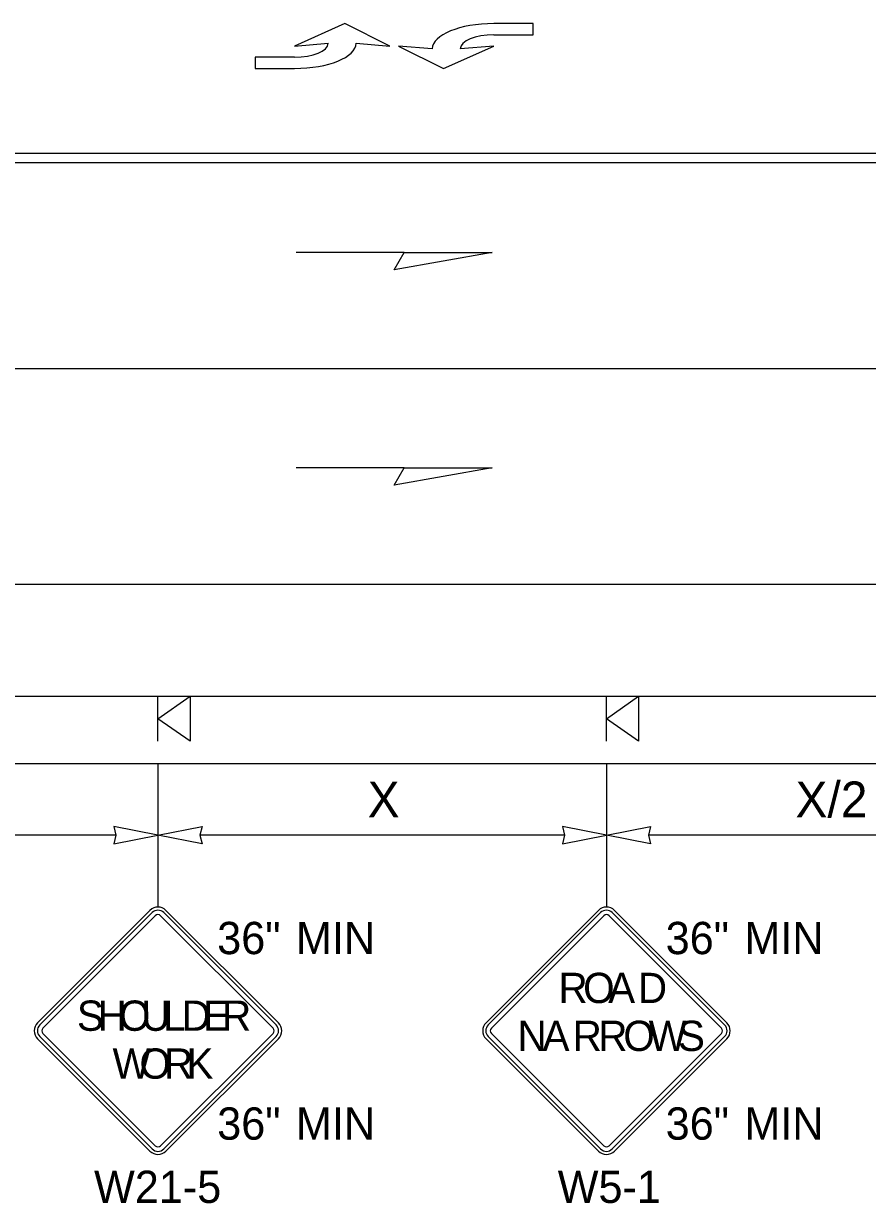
# Model space of a CAD drawing. Extents: x 99999.1 to 100096.1, y 99995 to 100010.7.
# Drawn here: x 100062.749 to 100064.63, y 100004.005 to 100006.636 of the extents above; entities that cross this region are included whole.
import ezdxf

# ---------------------------------------------------------------- set-up
doc = ezdxf.new("R2010")
doc.units = 0
for name, color, linetype in [('RD_ED_ShoulderPavedEdge', 7, 'Continuous'), ('RD_MK_LineEdgeWhite', 7, 'Continuous'), ('RD_MK_LineLane', 7, 'Continuous'), ('RD_MK_LineTwoWayLtTurn', 7, 'Continuous'), ('TR_SN_ConstructionSigns', 7, 'Continuous'), ('TR_WZ_PortableSignMountBlk-Org', 7, 'Continuous'), ('TR_WZ_WorkZoneDetails', 7, 'Continuous'), ('TR_WZ_WorkZoneTextCurrent', 7, 'Continuous')]:
    doc.layers.add(name, color=color, linetype=linetype)

msp = doc.modelspace()

# ---------------------------------------------------------------- linework, layer by layer
at = {"layer": 'RD_ED_ShoulderPavedEdge'}
msp.add_line((100060.8283, 100004.9857), (100074.8933, 100004.9857), dxfattribs=at)
at = {"layer": 'RD_MK_LineEdgeWhite'}
msp.add_line((100060.8283, 100005.3857), (100074.8933, 100005.3857), dxfattribs=at)
at = {"layer": 'RD_MK_LineLane'}
msp.add_lwpolyline([(100074.8933, 100005.8657), (100060.8283, 100005.8657)], dxfattribs=at)
at = {"layer": 'RD_MK_LineTwoWayLtTurn'}
msp.add_line((100060.8283, 100006.3257), (100074.8933, 100006.3257), dxfattribs=at)
msp.add_lwpolyline([(100074.8933, 100006.3457), (100060.8283, 100006.3457)], dxfattribs=at)
at = {"layer": 'TR_SN_ConstructionSigns'}
for p, q in [((100063.0307, 100004.6583), (100062.7801, 100004.4077)), ((100063.3171, 100004.4077), (100063.0665, 100004.6583)), ((100064.0307, 100004.6583), (100063.7801, 100004.4077)), ((100064.3171, 100004.4077), (100064.0665, 100004.6583)), ((100063.0357, 100004.6533), (100062.7851, 100004.4028)), ((100062.7921, 100004.3958), (100063.0426, 100004.6464)), ((100063.0546, 100004.6464), (100063.3052, 100004.3958)), ((100063.3121, 100004.4028), (100063.0615, 100004.6533)), ((100064.0357, 100004.6533), (100063.7851, 100004.4028)), ((100063.7921, 100004.3958), (100064.0426, 100004.6464)), ((100064.0546, 100004.6464), (100064.3052, 100004.3958)), ((100064.3121, 100004.4028), (100064.0615, 100004.6533)), ((100062.7801, 100004.3719), (100063.0307, 100004.1214)), ((100062.7851, 100004.3769), (100063.0357, 100004.1263)), ((100063.0426, 100004.1333), (100062.7921, 100004.3839)), ((100063.3052, 100004.3839), (100063.0546, 100004.1333)), ((100063.0615, 100004.1263), (100063.3121, 100004.3769)), ((100063.0665, 100004.1214), (100063.3171, 100004.3719)), ((100063.7801, 100004.3719), (100064.0307, 100004.1214)), ((100063.7851, 100004.3769), (100064.0357, 100004.1263)), ((100064.0426, 100004.1333), (100063.7921, 100004.3839)), ((100064.3052, 100004.3839), (100064.0546, 100004.1333)), ((100064.0615, 100004.1263), (100064.3121, 100004.3769)), ((100064.0665, 100004.1214), (100064.3171, 100004.3719))]:
    msp.add_line(p, q, dxfattribs=at)
for centre, radius, start, end in [((100063.0486, 100004.6404), 0.0253, 45, 135), ((100063.0486, 100004.6404), 0.0183, 45, 135), ((100064.0486, 100004.6404), 0.0253, 45, 135), ((100064.0486, 100004.6404), 0.0183, 45, 135), ((100063.0486, 100004.6404), 0.00844, 45, 135), ((100064.0486, 100004.6404), 0.00844, 45, 135), ((100062.798, 100004.3898), 0.0253, 135, 225), ((100062.798, 100004.3898), 0.0183, 135, 225), ((100062.798, 100004.3898), 0.00844, 135, 225), ((100063.2992, 100004.3898), 0.00844, 315, 45), ((100063.2992, 100004.3898), 0.0183, 315, 45), ((100063.2992, 100004.3898), 0.0253, 315, 45), ((100063.798, 100004.3898), 0.0253, 135, 225), ((100063.798, 100004.3898), 0.0183, 135, 225), ((100063.798, 100004.3898), 0.00844, 135, 225), ((100064.2992, 100004.3898), 0.00844, 315, 45), ((100064.2992, 100004.3898), 0.0183, 315, 45), ((100064.2992, 100004.3898), 0.0253, 315, 45), ((100063.0486, 100004.1393), 0.00844, 225, 315), ((100064.0486, 100004.1393), 0.00844, 225, 315), ((100063.0486, 100004.1393), 0.0253, 225, 315), ((100063.0486, 100004.1393), 0.0183, 225, 315), ((100064.0486, 100004.1393), 0.0253, 225, 315), ((100064.0486, 100004.1393), 0.0183, 225, 315)]:
    msp.add_arc(centre, radius, start, end, dxfattribs=at)
at = {"layer": 'TR_WZ_PortableSignMountBlk-Org'}
for p, q in [((100063.0486, 100005.0358), (100063.0486, 100005.1358)), ((100064.0486, 100005.0358), (100064.0486, 100005.1358))]:
    msp.add_line(p, q, dxfattribs=at)
for points in [[(100063.0486, 100005.0857), (100063.1204, 100005.1358), (100063.1204, 100005.0358)], [(100064.0486, 100005.0857), (100064.1204, 100005.1358), (100064.1204, 100005.0358)]]:
    msp.add_lwpolyline(points, close=True, dxfattribs=at)
at = {"layer": 'TR_WZ_WorkZoneDetails'}
for p, q in [((100063.5976, 100006.125), (100063.3565, 100006.125)), ((100063.5976, 100005.645), (100063.3565, 100005.645)), ((100061.4486, 100005.1358), (100065.9101, 100005.1358)), ((100063.0486, 100004.986), (100063.0486, 100004.6657)), ((100064.0486, 100004.986), (100064.0486, 100004.6657)), ((100062.9549, 100004.8257), (100062.3423, 100004.8257)), ((100063.9549, 100004.8257), (100063.1423, 100004.8257)), ((100064.9549, 100004.8257), (100064.1423, 100004.8257))]:
    msp.add_line(p, q, dxfattribs=at)
for points in [[(100063.4903, 100006.5919), (100063.5653, 100006.5857), (100063.4653, 100006.6357), (100063.3528, 100006.5857), (100063.4278, 100006.5919)], [(100063.7978, 100006.6107), (100063.8853, 100006.6107), (100063.8853, 100006.6357), (100063.7978, 100006.6357)], [(100063.6603, 100006.5795), (100063.5853, 100006.5857), (100063.6853, 100006.5357), (100063.7978, 100006.5857), (100063.7228, 100006.5795)], [(100063.3528, 100006.5607), (100063.2653, 100006.5607), (100063.2653, 100006.5357), (100063.3528, 100006.5357)]]:
    msp.add_lwpolyline(points, dxfattribs=at)
for points in [[(100063.7941, 100006.125), (100063.5753, 100006.0864), (100063.5976, 100006.125)], [(100063.7941, 100005.645), (100063.5753, 100005.6064), (100063.5976, 100005.645)], [(100063.0486, 100004.8257), (100062.9503, 100004.845), (100062.9549, 100004.8257), (100062.9503, 100004.8065)], [(100063.0486, 100004.8257), (100063.1469, 100004.845), (100063.1423, 100004.8257), (100063.1469, 100004.8065)], [(100064.0486, 100004.8257), (100063.9503, 100004.845), (100063.9549, 100004.8257), (100063.9503, 100004.8065)], [(100064.0486, 100004.8257), (100064.1469, 100004.845), (100064.1423, 100004.8257), (100064.1469, 100004.8065)]]:
    msp.add_lwpolyline(points, close=True, dxfattribs=at)
for centre, major_axis, ratio, start_param in [((100063.7978, 100006.5795), (-0.1375, 0), 0.40879, 4.712524), ((100063.7978, 100006.5795), (-0.075, 0), 0.41611, 4.712518), ((100063.3528, 100006.5919), (0.075, 0), 0.41611, 4.712518), ((100063.3528, 100006.5919), (0.1375, 0), 0.40879, 4.712524)]:
    msp.add_ellipse(centre, major_axis=major_axis, ratio=ratio, start_param=start_param, end_param=6.283185, dxfattribs=at)

# ---------------------------------------------------------------- texts
at = {"layer": 'TR_SN_ConstructionSigns'}
for s, p in [('36"', (100063.1807, 100004.5607)), ('MIN', (100063.3562, 100004.5607)), ('36"', (100064.1807, 100004.5607)), ('MIN', (100064.3562, 100004.5607)), ('36"', (100063.1807, 100004.147)), ('MIN', (100063.3562, 100004.147)), ('36"', (100064.1807, 100004.147)), ('MIN', (100064.3562, 100004.147)), ('W21-5', (100062.9061, 100004.0059)), ('W5-1', (100063.94, 100004.0059))]:
    msp.add_text(s, height=0.072, rotation=360, dxfattribs=at).set_placement(p)
for s, p in [('R', (100063.9417, 100004.4517)), ('O', (100063.9966, 100004.4517)), ('A', (100064.0524, 100004.4517)), ('D', (100064.1187, 100004.4517)), ('S', (100062.8679, 100004.3898)), ('H', (100062.914, 100004.3898)), ('O', (100062.9616, 100004.3898)), ('U', (100063.0113, 100004.3898)), ('L', (100063.0599, 100004.3898)), ('D', (100063.1012, 100004.3898)), ('E', (100063.1488, 100004.3898)), ('R', (100063.1915, 100004.3898)), ('N', (100063.8503, 100004.3448)), ('A', (100063.9061, 100004.3448)), ('R', (100063.9733, 100004.3448)), ('R', (100064.0304, 100004.3448)), ('O', (100064.0862, 100004.3448)), ('W', (100064.1427, 100004.3448)), ('S', (100064.208, 100004.3448)), ('W', (100062.9474, 100004.283)), ('O', (100063.0074, 100004.283)), ('R', (100063.0619, 100004.283)), ('K', (100063.1121, 100004.283))]:
    msp.add_text(s, height=0.0675, dxfattribs=at).set_placement(p)
at = {"layer": 'TR_WZ_WorkZoneTextCurrent'}
for s, p in [('X/2', (100064.4701, 100004.8657)), ('X', (100063.5161, 100004.8657))]:
    msp.add_text(s, height=0.08, rotation=360, dxfattribs=at).set_placement(p)

doc.saveas('drawing.dxf')
